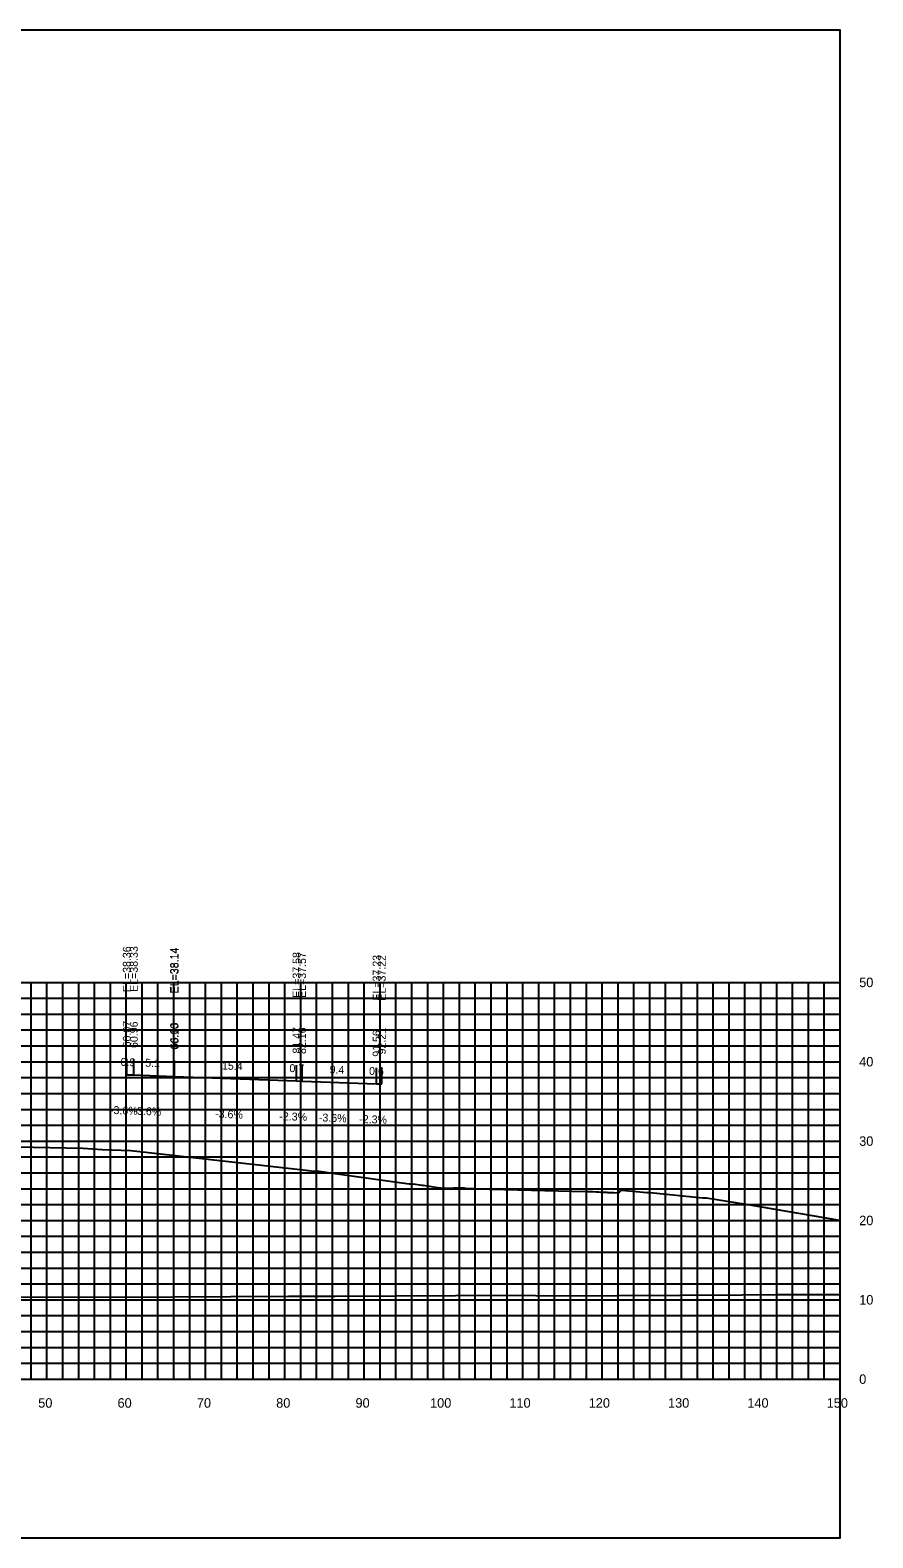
# Model space of a CAD drawing. Extents: x 1800880 to 1818864, y 245271 to 250560.
# Drawn here: x 1810238.3 to 1810344.5, y 247793.8 to 247983.8 of the extents above; entities that cross this region are included whole.
import ezdxf

# ---------------------------------------------------------------- set-up
doc = ezdxf.new("R2010")
doc.units = 0
for name, color, linetype in [('33', 7, 'Continuous'), ('ANNO-TXT', 7, 'Continuous'), ('CL-CNST', 7, 'Continuous'), ('DESIGN - DRAINAGE - Bridges', 7, 'Continuous'), ('Level 37', 7, 'Continuous'), ('Level 46', 7, 'Continuous'), ('Level 62', 7, 'Continuous'), ('SHT-BDR', 7, 'Continuous')]:
    doc.layers.add(name, color=color, linetype=linetype)

msp = doc.modelspace()

# ---------------------------------------------------------------- linework, layer by layer
at = {"layer": 'CL-CNST'}
msp.add_lwpolyline([(1810236.54, 247843.09), (1810244.89, 247842.9), (1810247.34, 247842.75), (1810250.97, 247842.61), (1810270.77, 247840.37), (1810273.01, 247840.14), (1810273.7, 247840.07), (1810273.71, 247840.07), (1810274.02, 247840.03), (1810274.17, 247840), (1810274.69, 247840), (1810275.32, 247839.92), (1810276.36, 247839.76), (1810286.04, 247838.41), (1810286.43, 247838.41), (1810286.54, 247838.41), (1810287.69, 247838.26), (1810287.8, 247838.25), (1810289.93, 247837.89), (1810289.95, 247837.89), (1810289.97, 247837.89), (1810289.99, 247837.89), (1810290.01, 247837.88), (1810290.03, 247837.88), (1810290.04, 247837.88), (1810290.06, 247837.88), (1810290.07, 247837.88), (1810290.09, 247837.88), (1810290.1, 247837.88), (1810290.11, 247837.88), (1810291.64, 247837.89), (1810291.76, 247837.89), (1810291.89, 247837.89), (1810292.04, 247837.9), (1810292.22, 247837.9), (1810292.44, 247837.9), (1810292.7, 247837.9), (1810292.98, 247837.91), (1810292.99, 247837.9), (1810293.06, 247837.88), (1810293.09, 247837.87), (1810293.1, 247837.87), (1810293.11, 247837.86), (1810293.12, 247837.86), (1810293.13, 247837.86), (1810293.13, 247837.86), (1810293.13, 247837.86), (1810296.14, 247837.74), (1810296.35, 247837.73), (1810306.56, 247837.47), (1810308.33, 247837.45), (1810308.37, 247837.45), (1810308.73, 247837.45), (1810309.18, 247837.43), (1810309.6, 247837.41), (1810309.94, 247837.39), (1810310.22, 247837.38), (1810310.45, 247837.37), (1810310.64, 247837.36), (1810310.81, 247837.35), (1810310.95, 247837.35), (1810311.08, 247837.34), (1810311.19, 247837.34), (1810311.28, 247837.33), (1810311.37, 247837.33), (1810311.45, 247837.32), (1810311.52, 247837.32), (1810311.59, 247837.32), (1810311.65, 247837.31), (1810311.67, 247837.31), (1810311.7, 247837.31), (1810311.74, 247837.31), (1810311.77, 247837.3), (1810311.81, 247837.3), (1810311.84, 247837.3), (1810312.42, 247837.26), (1810312.7, 247837.58), (1810312.84, 247837.6), (1810312.85, 247837.6), (1810316, 247837.34), (1810316.17, 247837.33), (1810316.44, 247837.34), (1810323.03, 247836.64), (1810323.25, 247836.64), (1810323.54, 247836.63), (1810328.47, 247835.83), (1810340.29, 247833.85), (1810340.38, 247833.85)], dxfattribs=at)
at = {"layer": 'DESIGN - DRAINAGE - Bridges'}
for p, q in [((1810340.38, 247813.8), (1810340.38, 247863.8)), ((1810340.44, 247863.8), (1810340.38, 247863.8)), ((1810340.44, 247853.8), (1810340.38, 247853.8)), ((1810340.44, 247843.8), (1810340.38, 247843.8)), ((1810340.44, 247833.8), (1810340.38, 247833.8)), ((1810340.44, 247823.8), (1810340.38, 247823.8)), ((1810040.38, 247813.8), (1810340.38, 247813.8)), ((1810240.38, 247813.74), (1810240.38, 247813.8)), ((1810250.38, 247813.74), (1810250.38, 247813.8)), ((1810260.38, 247813.74), (1810260.38, 247813.8)), ((1810270.38, 247813.74), (1810270.38, 247813.8)), ((1810280.38, 247813.74), (1810280.38, 247813.8)), ((1810290.38, 247813.74), (1810290.38, 247813.8)), ((1810300.38, 247813.74), (1810300.38, 247813.8)), ((1810310.38, 247813.74), (1810310.38, 247813.8)), ((1810320.38, 247813.74), (1810320.38, 247813.8)), ((1810330.38, 247813.74), (1810330.38, 247813.8)), ((1810340.38, 247813.74), (1810340.38, 247813.8)), ((1810340.44, 247813.8), (1810340.38, 247813.8))]:
    msp.add_line(p, q, dxfattribs=at)
at = {"layer": 'Level 37'}
for p, q in [((1810250.45, 247852.16), (1810250.45, 247854.16)), ((1810251.33, 247852.13), (1810251.33, 247854.13)), ((1810256.41, 247851.94), (1810256.41, 247853.94)), ((1810256.48, 247851.94), (1810256.48, 247853.94)), ((1810271.85, 247851.38), (1810271.85, 247853.38)), ((1810272.54, 247851.37), (1810272.54, 247853.37)), ((1810281.94, 247851.03), (1810281.94, 247853.03)), ((1810282.59, 247851.01), (1810282.59, 247853.01))]:
    msp.add_line(p, q, dxfattribs=at)
msp.add_lwpolyline([(1810040.38, 247793.8), (1810340.38, 247793.8), (1810340.38, 247983.8), (1810040.38, 247983.8)], close=True, dxfattribs=at)
at = {"layer": 'Level 46'}
for p, q in [((1810040.38, 247863.8), (1810340.38, 247863.8)), ((1810238.38, 247813.8), (1810238.38, 247863.8)), ((1810240.38, 247813.8), (1810240.38, 247863.8)), ((1810242.38, 247813.8), (1810242.38, 247863.8)), ((1810244.38, 247813.8), (1810244.38, 247863.8)), ((1810246.38, 247813.8), (1810246.38, 247863.8)), ((1810248.38, 247813.8), (1810248.38, 247863.8)), ((1810250.38, 247813.8), (1810250.38, 247863.8)), ((1810252.38, 247813.8), (1810252.38, 247863.8)), ((1810254.38, 247813.8), (1810254.38, 247863.8)), ((1810256.38, 247813.8), (1810256.38, 247863.8)), ((1810258.38, 247813.8), (1810258.38, 247863.8)), ((1810260.38, 247813.8), (1810260.38, 247863.8)), ((1810262.38, 247813.8), (1810262.38, 247863.8)), ((1810264.38, 247813.8), (1810264.38, 247863.8)), ((1810266.38, 247813.8), (1810266.38, 247863.8)), ((1810268.38, 247813.8), (1810268.38, 247863.8)), ((1810270.38, 247813.8), (1810270.38, 247863.8)), ((1810272.38, 247813.8), (1810272.38, 247863.8)), ((1810274.38, 247813.8), (1810274.38, 247863.8)), ((1810276.38, 247813.8), (1810276.38, 247863.8)), ((1810278.38, 247813.8), (1810278.38, 247863.8)), ((1810280.38, 247813.8), (1810280.38, 247863.8)), ((1810282.38, 247813.8), (1810282.38, 247863.8)), ((1810284.38, 247813.8), (1810284.38, 247863.8)), ((1810286.38, 247813.8), (1810286.38, 247863.8)), ((1810288.38, 247813.8), (1810288.38, 247863.8)), ((1810290.38, 247813.8), (1810290.38, 247863.8)), ((1810292.38, 247813.8), (1810292.38, 247863.8)), ((1810294.38, 247813.8), (1810294.38, 247863.8)), ((1810296.38, 247813.8), (1810296.38, 247863.8)), ((1810298.38, 247813.8), (1810298.38, 247863.8)), ((1810300.38, 247813.8), (1810300.38, 247863.8)), ((1810302.38, 247813.8), (1810302.38, 247863.8)), ((1810304.38, 247813.8), (1810304.38, 247863.8)), ((1810306.38, 247813.8), (1810306.38, 247863.8)), ((1810308.38, 247813.8), (1810308.38, 247863.8)), ((1810310.38, 247813.8), (1810310.38, 247863.8)), ((1810312.38, 247813.8), (1810312.38, 247863.8)), ((1810314.38, 247813.8), (1810314.38, 247863.8)), ((1810316.38, 247813.8), (1810316.38, 247863.8)), ((1810318.38, 247813.8), (1810318.38, 247863.8)), ((1810320.38, 247813.8), (1810320.38, 247863.8)), ((1810322.38, 247813.8), (1810322.38, 247863.8)), ((1810324.38, 247813.8), (1810324.38, 247863.8)), ((1810326.38, 247813.8), (1810326.38, 247863.8)), ((1810328.38, 247813.8), (1810328.38, 247863.8)), ((1810330.38, 247813.8), (1810330.38, 247863.8)), ((1810332.38, 247813.8), (1810332.38, 247863.8)), ((1810334.38, 247813.8), (1810334.38, 247863.8)), ((1810336.38, 247813.8), (1810336.38, 247863.8)), ((1810338.38, 247813.8), (1810338.38, 247863.8)), ((1810340.38, 247813.8), (1810340.38, 247863.8)), ((1810040.38, 247861.8), (1810340.38, 247861.8)), ((1810040.38, 247859.8), (1810340.38, 247859.8)), ((1810040.38, 247857.8), (1810340.38, 247857.8)), ((1810040.38, 247855.8), (1810340.38, 247855.8)), ((1810040.38, 247853.8), (1810340.38, 247853.8)), ((1810040.38, 247851.8), (1810340.38, 247851.8)), ((1810040.38, 247849.8), (1810340.38, 247849.8)), ((1810040.38, 247847.8), (1810340.38, 247847.8)), ((1810040.38, 247845.8), (1810340.38, 247845.8)), ((1810040.38, 247843.8), (1810340.38, 247843.8)), ((1810040.38, 247841.8), (1810340.38, 247841.8)), ((1810040.38, 247839.8), (1810340.38, 247839.8)), ((1810040.38, 247837.8), (1810340.38, 247837.8)), ((1810040.38, 247835.8), (1810340.38, 247835.8)), ((1810040.38, 247833.8), (1810340.38, 247833.8)), ((1810040.38, 247831.8), (1810340.38, 247831.8)), ((1810040.38, 247829.8), (1810340.38, 247829.8)), ((1810040.38, 247827.8), (1810340.38, 247827.8)), ((1810040.38, 247825.8), (1810340.38, 247825.8)), ((1810040.38, 247823.8), (1810340.38, 247823.8)), ((1810040.38, 247821.8), (1810340.38, 247821.8)), ((1810040.38, 247819.8), (1810340.38, 247819.8)), ((1810040.38, 247817.8), (1810340.38, 247817.8)), ((1810040.38, 247815.8), (1810340.38, 247815.8)), ((1810040.38, 247813.8), (1810340.38, 247813.8))]:
    msp.add_line(p, q, dxfattribs=at)
at = {"layer": 'Level 62'}
for points in [[(1810250.45, 247852.16), (1810251.33, 247852.13), (1810256.41, 247851.94), (1810256.48, 247851.94), (1810271.85, 247851.38), (1810272.54, 247851.37), (1810281.94, 247851.03), (1810282.59, 247851.01)], [(1810040.38, 247825.07), (1810054.69, 247824.89), (1810062.63, 247824.84), (1810082.44, 247824.65), (1810093.94, 247824.6), (1810110.2, 247824.47), (1810124.43, 247824.43), (1810137.95, 247824.3), (1810154.35, 247824.27), (1810165.71, 247824.2), (1810183.86, 247824.2), (1810193.46, 247824.13), (1810213.06, 247824.16), (1810221.22, 247824.1), (1810242.04, 247824.17), (1810248.97, 247824.15), (1810270.84, 247824.25), (1810276.73, 247824.26), (1810299.49, 247824.39), (1810304.48, 247824.3), (1810328.03, 247824.44), (1810332.24, 247824.48), (1810336.12, 247824.46), (1810340.38, 247824.48)]]:
    msp.add_lwpolyline(points, dxfattribs=at)

# ---------------------------------------------------------------- texts
for s, p in [('50', (1810239.28, 247810.2)), ('60', (1810249.28, 247810.2)), ('70', (1810259.28, 247810.2)), ('80', (1810269.28, 247810.2)), ('90', (1810279.28, 247810.2)), ('100', (1810288.68, 247810.2)), ('110', (1810298.68, 247810.2)), ('120', (1810308.68, 247810.2)), ('130', (1810318.68, 247810.2)), ('140', (1810328.68, 247810.2)), ('150', (1810338.68, 247810.2))]:
    msp.add_text(s, height=1.2).set_placement(p)
at = {"layer": '33'}
for s, p in [('50', (1810342.78, 247863.2)), ('40', (1810342.78, 247853.2)), ('30', (1810342.78, 247843.2)), ('20', (1810342.78, 247833.2)), ('10', (1810342.78, 247823.2)), ('0', (1810342.78, 247813.2))]:
    msp.add_text(s, height=1.2, dxfattribs=at).set_placement(p)
at = {"layer": 'ANNO-TXT'}
for s, rotation, p in [('0.9', 357.9493, (1810249.65, 247853.29)), ('5.1', 357.9123, (1810252.76, 247853.18)), ('15.4', 357.9214, (1810262.43, 247852.83)), ('0.7', 358.665, (1810270.94, 247852.5)), ('9.4', 357.9457, (1810276, 247852.34)), ('0.6', 358.6802, (1810280.98, 247852.15)), ('-3.6%', 357.9493, (1810248.31, 247847.23)), ('-3.6%', 357.9123, (1810251.28, 247847.13)), ('-3.6%', 357.9214, (1810261.57, 247846.75)), ('-2.3%', 358.665, (1810269.67, 247846.43)), ('-3.6%', 357.9457, (1810274.65, 247846.29)), ('-2.3%', 358.6802, (1810279.74, 247846.08))]:
    msp.add_text(s, height=1, rotation=rotation, dxfattribs=at).set_placement(p)
at = {"layer": 'SHT-BDR'}
for s, p in [('EL=38.33', (1810251.83, 247862.6)), ('EL=38.36', (1810250.95, 247862.58)), ('EL=38.14', (1810256.91, 247862.41)), ('EL=38.14', (1810256.98, 247862.41)), ('EL=37.58', (1810272.35, 247861.86)), ('EL=37.57', (1810273.04, 247861.84)), ('EL=37.23', (1810282.44, 247861.5)), ('EL=37.22', (1810283.09, 247861.49)), ('60.07', (1810250.95, 247855.61)), ('60.96', (1810251.83, 247855.53)), ('66.03', (1810256.91, 247855.39)), ('66.10', (1810256.98, 247855.31)), ('81.47', (1810272.35, 247854.83)), ('82.16', (1810273.04, 247854.77)), ('91.56', (1810282.44, 247854.43)), ('92.21', (1810283.09, 247854.72))]:
    msp.add_text(s, height=1, rotation=90, dxfattribs=at).set_placement(p)

doc.saveas('drawing.dxf')
